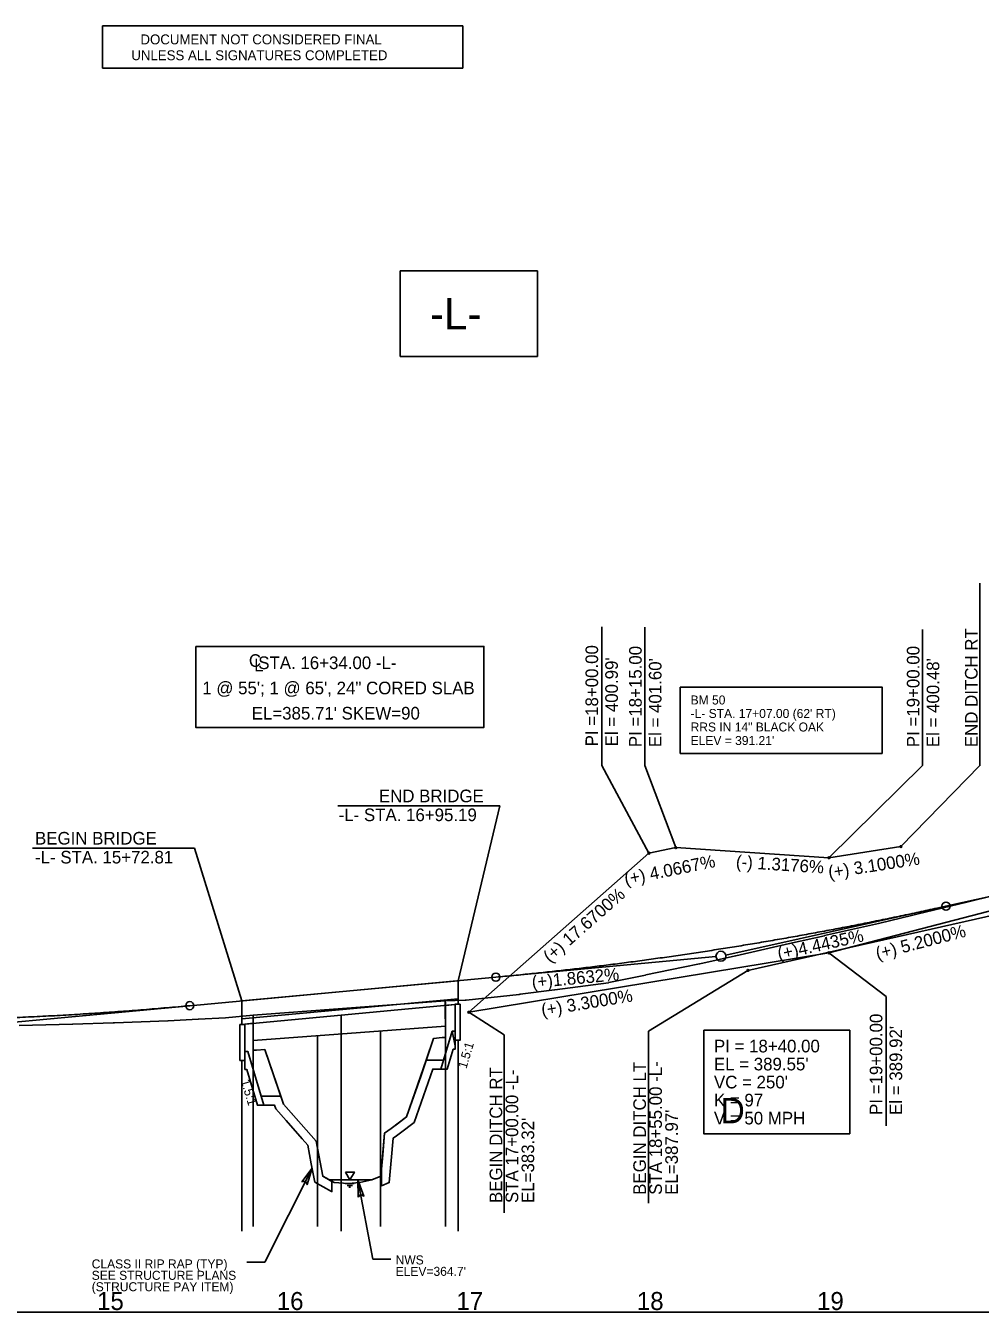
# Model space of a CAD drawing. Extents: x 2099451 to 2100919, y 990328 to 992828.
# Drawn here: x 2099966 to 2100496, y 991578 to 992293 of the extents above; entities that cross this region are included whole.
import ezdxf

# ---------------------------------------------------------------- set-up
doc = ezdxf.new("R2010")
doc.units = 0
for name, color, linetype in [('CTL Bench Mark Text', 7, 'Continuous'), ('Exist Profile Cell', 7, 'Continuous'), ('Exist Structure Major Deck Tunnel Box Culvert', 7, 'Continuous'), ('Exist Vertical Profile Ground Line', 7, 'Continuous'), ('Exist Vertical Profile Horizontal Axis Label Major', 7, 'Continuous'), ('Prop Drainage Structure Bridge', 7, 'Continuous'), ('Prop Drainage Structure Bridge Opening', 7, 'Continuous'), ('Prop Drainage Structure Bridge Opening Label', 7, 'Continuous'), ('Prop Erosion Rip Rap Class II', 7, 'Continuous'), ('Prop Plan Preparation Excavation Hatching', 7, 'Continuous'), ('Prop Plan Preparation Plan View Label', 7, 'Continuous'), ('Prop Plan Preparation Stream Water Surface', 7, 'Continuous'), ('Prop Plan Preparation Water Surface Symbol CELL', 7, 'Continuous'), ('Prop Roadway Bridge', 7, 'Continuous'), ('Prop Vertical Profile Curve Label', 7, 'Continuous'), ('Prop Vertical Profile Ditch Grade Left', 7, 'Continuous'), ('Prop Vertical Profile Ditch Grade Left Label', 7, 'Continuous'), ('Prop Vertical Profile Ditch Grade Right', 7, 'Continuous'), ('Prop Vertical Profile Ditch Grade Right Label', 7, 'Continuous'), ('Prop Vertical Profile Grade', 7, 'Continuous'), ('Prop Vertical Profile Grade Label', 7, 'Continuous'), ('Prop VPI Ditch Grade Left Label', 7, 'Continuous'), ('Prop VPI Ditch Grade Right Label', 7, 'Continuous'), ('Prop VPI Label', 7, 'Continuous'), ('Scratch_Level_2', 7, 'Continuous'), ('Typical Terminator CELL', 7, 'Continuous')]:
    doc.layers.add(name, color=color, linetype=linetype)

msp = doc.modelspace()

# ---------------------------------------------------------------- linework, layer by layer
at = {"layer": 'CTL Bench Mark Text'}
msp.add_lwpolyline([(2100329.53, 991925.5), (2100441.65, 991925.5), (2100441.65, 991888.64), (2100329.53, 991888.64)], close=True, dxfattribs=at)
at = {"layer": 'Exist Profile Cell'}
msp.add_line((2099512.14, 991578.31), (2100912.14, 991578.31), dxfattribs=at)
at = {"layer": 'Exist Structure Major Deck Tunnel Box Culvert'}
for p, q in [((2100092.35, 991743.27), (2100199.07, 991751.21)), ((2100199.12, 991750.52), (2100199.12, 991625.9)), ((2100092.4, 991742.57), (2100092.4, 991625.89)), ((2100092.38, 991729.23), (2100199.12, 991737.18)), ((2100163.11, 991734.5), (2100163.11, 991625.89)), ((2100128.15, 991731.9), (2100128.15, 991625.89))]:
    msp.add_line(p, q, dxfattribs=at)
at = {"layer": 'Exist Vertical Profile Ground Line'}
for points in [[(2100340.31, 991771.72), (2100340.37, 991771.73), (2100360.29, 991776.24), (2100360.34, 991776.26), (2100390.21, 991783.02), (2100390.32, 991783.04), (2100409.64, 991787.44), (2100409.7, 991787.45), (2100439.6, 991794.26), (2100439.66, 991794.27), (2100458.77, 991798.86), (2100461.71, 991799.57), (2100488.7, 991806.04), (2100488.78, 991806.06), (2100504.54, 991809.85)], [(2099962.4, 991737.64), (2099991.95, 991738.28), (2099992.27, 991738.29), (2100014.61, 991739.06), (2100015.06, 991739.08), (2100015.35, 991739.1), (2100044.92, 991740.11), (2100045.21, 991740.13), (2100061.86, 991740.99), (2100062.03, 991741), (2100077.04, 991741.77), (2100092.35, 991743.27), (2100092.4, 991723.81), (2100094.24, 991723.91), (2100098.82, 991724.16), (2100109.29, 991693.81), (2100127.38, 991673.31), (2100131.02, 991653.81), (2100137.32, 991650.31), (2100145.12, 991649.81), (2100151.66, 991650.31), (2100158.3, 991651.81), (2100163.2, 991653.81), (2100165.38, 991677.81), (2100169.05, 991680.31), (2100177.49, 991686.81), (2100185.66, 991709.86), (2100192.48, 991730.31), (2100197.25, 991730.81), (2100199.12, 991730.81), (2100199.07, 991751.21), (2100210.18, 991751.67), (2100210.61, 991751.71), (2100240.15, 991754.85), (2100240.18, 991754.85), (2100240.64, 991754.9), (2100259.75, 991757.41), (2100259.94, 991757.43), (2100289.62, 991761.33), (2100289.85, 991761.38), (2100310.35, 991765.58), (2100310.42, 991765.6), (2100331.26, 991769.87), (2100340.31, 991771.72)]]:
    msp.add_lwpolyline(points, dxfattribs=at)
at = {"layer": 'Prop Drainage Structure Bridge'}
for p, q in [((2100086.14, 991751.26), (2100206.14, 991762.44)), ((2100206.14, 991749.38), (2100206.14, 991762.44)), ((2100086.14, 991738.2), (2100086.14, 991751.26)), ((2100086.14, 991738.2), (2100206.14, 991749.38)), ((2100141.14, 991623.39), (2100141.14, 991743.33)), ((2100206.14, 991623.4), (2100206.14, 991729.38)), ((2100086.14, 991623.39), (2100086.14, 991718.2))]:
    msp.add_line(p, q, dxfattribs=at)
for points in [[(2100204.52, 991729.38), (2100207.27, 991729.38), (2100207.27, 991749.38), (2100204.52, 991749.38)], [(2100085.02, 991738.2), (2100087.77, 991738.2), (2100087.77, 991718.2), (2100085.02, 991718.2)]]:
    msp.add_lwpolyline(points, close=True, dxfattribs=at)
at = {"layer": 'Prop Drainage Structure Bridge Opening'}
for p, q in [((2100198.09, 991718.31), (2100188.48, 991718.31)), ((2100200.19, 991713.31), (2100196.59, 991713.31)), ((2100098.34, 991693.31), (2100094.74, 991693.31))]:
    msp.add_line(p, q, dxfattribs=at)
for points in [[(2100196.59, 991713.31), (2100202.91, 991734.38), (2100204.52, 991734.38), (2100204.52, 991724.38), (2100203.52, 991724.38), (2100200.19, 991713.31)], [(2100098.34, 991693.31), (2100089.37, 991723.2), (2100087.77, 991723.2), (2100087.77, 991713.2), (2100088.77, 991713.2), (2100094.74, 991693.31)]]:
    msp.add_lwpolyline(points, dxfattribs=at)
at = {"layer": 'Prop Erosion Rip Rap Class II'}
for points in [[(2100202.91, 991734.38), (2100204.52, 991734.38), (2100204.52, 991724.38), (2100203.52, 991724.38), (2100200.19, 991713.31), (2100196.59, 991713.31)], [(2100087.77, 991723.2), (2100089.37, 991723.2), (2100098.34, 991693.31), (2100094.74, 991693.31), (2100088.77, 991713.2), (2100087.77, 991713.2)], [(2100198.09, 991718.31), (2100188.48, 991718.31), (2100177.49, 991686.81), (2100174.17, 991684.25), (2100173.27, 991683.56), (2100169.05, 991680.31), (2100165.38, 991677.81), (2100164.29, 991665.81), (2100163.55, 991657.69), (2100163.55, 991648.55), (2100167.91, 991650.33), (2100169.03, 991662.67), (2100170.15, 991675.01), (2100171.98, 991676.26), (2100174.21, 991677.97), (2100181.71, 991683.75), (2100192.08, 991713.31), (2100196.59, 991713.31)], [(2100096.84, 991698.31), (2100107.74, 991698.31), (2100109.29, 991693.81), (2100110.75, 991692.15), (2100127.38, 991673.31), (2100129.2, 991663.56), (2100131.02, 991653.81), (2100136.14, 991650.97), (2100136.14, 991645.37), (2100135.88, 991645.39), (2100126.54, 991650.58), (2100124.63, 991660.81), (2100122.72, 991671.03), (2100119.56, 991674.61), (2100110.75, 991684.73), (2100104.89, 991691.24), (2100104.13, 991693.32), (2100098.34, 991693.31)]]:
    msp.add_lwpolyline(points, close=True, dxfattribs=at)
at = {"layer": 'Prop Plan Preparation Excavation Hatching'}
for points in [[(2100199.12, 991730.81), (2100199.12, 991748.73), (2100204.52, 991749.23), (2100204.52, 991726.32), (2100202.91, 991734.38), (2100198.09, 991718.31), (2100188.48, 991718.31), (2100192.48, 991730.31), (2100197.25, 991730.81)], [(2100087.77, 991738.36), (2100092.36, 991738.78), (2100092.4, 991723.81), (2100094.24, 991723.91), (2100098.82, 991724.16), (2100107.74, 991698.31), (2100096.84, 991698.31), (2100089.37, 991723.2), (2100087.77, 991723.2)]]:
    msp.add_lwpolyline(points, close=True, dxfattribs=at)
at = {"layer": 'Prop Plan Preparation Plan View Label'}
for p, q in [((2100125.08, 991658.37), (2100098.75, 991606.09)), ((2100150.49, 991651.81), (2100158.83, 991607.85)), ((2100098.75, 991606.09), (2100088.75, 991606.09)), ((2100158.83, 991607.85), (2100168.83, 991607.85))]:
    msp.add_line(p, q, dxfattribs=at)
msp.add_lwpolyline([(2100119.43, 991650.73), (2100125.08, 991658.37), (2100122.33, 991649.2), (2100121.38, 991651.02)], close=True, dxfattribs=at)
at = {"layer": 'Prop Plan Preparation Stream Water Surface'}
msp.add_line((2100134.62, 991651.81), (2100158.3, 991651.81), dxfattribs=at)
at = {"layer": 'Prop Plan Preparation Water Surface Symbol CELL'}
for p, q in [((2100143.49, 991649.78), (2100148.49, 991649.78)), ((2100144.49, 991648.78), (2100147.49, 991648.78)), ((2100145.49, 991647.78), (2100146.49, 991647.78))]:
    msp.add_line(p, q, dxfattribs=at)
msp.add_lwpolyline([(2100143.56, 991656.15), (2100148.56, 991656.15), (2100146.06, 991651.81)], close=True, dxfattribs=at)
at = {"layer": 'Prop Roadway Bridge'}
for p, q in [((2100206.14, 991762.44), (2100206.14, 991752.44)), ((2100206.14, 991752.44), (2100086.14, 991741.26)), ((2100086.14, 991751.26), (2100086.14, 991741.26))]:
    msp.add_line(p, q, dxfattribs=at)
at = {"layer": 'Prop Vertical Profile Curve Label'}
for centre in [(2100477.14, 991803.81), (2100227.14, 991764.4), (2100057.14, 991748.56)]:
    msp.add_circle(centre, 2.25, dxfattribs=at)
at = {"layer": 'Prop Vertical Profile Ditch Grade Left'}
msp.add_line((2100367.14, 991768.16), (2100612.14, 991823.31), dxfattribs=at)
at = {"layer": 'Prop Vertical Profile Ditch Grade Left Label'}
for p, q in [((2100367.14, 991768.16), (2100311.84, 991734.42)), ((2100311.84, 991734.42), (2100311.84, 991638.81))]:
    msp.add_line(p, q, dxfattribs=at)
at = {"layer": 'Prop Vertical Profile Ditch Grade Right'}
for points in [[(2100212.14, 991744.91), (2100312.14, 991833.26), (2100327.14, 991836.31), (2100412.14, 991830.71), (2100452.14, 991836.91)], [(2100212.14, 991744.91), (2100412.14, 991777.91), (2100612.14, 991829.91)]]:
    msp.add_lwpolyline(points, dxfattribs=at)
at = {"layer": 'Prop Vertical Profile Grade'}
for p, q in [((2100477.14, 991803.81), (2100612.14, 991833.81)), ((2100057.14, 991748.56), (2100227.14, 991764.4))]:
    msp.add_line(p, q, dxfattribs=at)
for points in [[(2100227.14, 991764.4), (2100232.14, 991764.87), (2100237.14, 991765.35), (2100242.14, 991765.85), (2100247.14, 991766.36), (2100252.14, 991766.89), (2100257.14, 991767.42), (2100262.14, 991767.97), (2100267.14, 991768.54), (2100272.14, 991769.11), (2100277.14, 991769.7), (2100282.14, 991770.3), (2100287.14, 991770.91), (2100292.14, 991771.54), (2100297.14, 991772.18), (2100302.14, 991772.83), (2100307.14, 991773.5), (2100312.14, 991774.18), (2100317.14, 991774.87), (2100322.14, 991775.58), (2100327.14, 991776.29), (2100332.14, 991777.02), (2100337.14, 991777.77), (2100342.14, 991778.52), (2100347.14, 991779.29), (2100352.14, 991780.07), (2100357.14, 991780.87), (2100362.14, 991781.68), (2100367.14, 991782.5), (2100372.14, 991783.33), (2100377.14, 991784.18), (2100382.14, 991785.04), (2100387.14, 991785.91), (2100392.14, 991786.79), (2100397.14, 991787.69), (2100402.14, 991788.6), (2100407.14, 991789.53), (2100412.14, 991790.46), (2100417.14, 991791.41), (2100422.14, 991792.37), (2100427.14, 991793.35), (2100432.14, 991794.34), (2100437.14, 991795.34), (2100442.14, 991796.35), (2100447.14, 991797.38), (2100452.14, 991798.42), (2100457.14, 991799.47), (2100462.14, 991800.54), (2100467.14, 991801.62), (2100472.14, 991802.71), (2100477.14, 991803.81)], [(2099737.14, 991745.25), (2099743.54, 991744.8), (2099749.94, 991744.37), (2099756.34, 991743.96), (2099762.74, 991743.57), (2099769.14, 991743.2), (2099775.54, 991742.85), (2099781.94, 991742.53), (2099788.34, 991742.22), (2099794.74, 991741.94), (2099801.14, 991741.67), (2099807.54, 991741.43), (2099813.94, 991741.21), (2099820.34, 991741.01), (2099826.74, 991740.84), (2099833.14, 991740.68), (2099839.54, 991740.54), (2099845.94, 991740.43), (2099852.34, 991740.34), (2099858.74, 991740.27), (2099865.14, 991740.21), (2099871.54, 991740.19), (2099877.94, 991740.18), (2099884.34, 991740.19), (2099890.74, 991740.22), (2099897.14, 991740.28), (2099903.54, 991740.36), (2099909.94, 991740.45), (2099916.34, 991740.57), (2099922.74, 991740.71), (2099929.14, 991740.88), (2099935.54, 991741.06), (2099941.94, 991741.26), (2099948.34, 991741.49), (2099954.74, 991741.73), (2099961.14, 991742), (2099967.54, 991742.29), (2099973.94, 991742.6), (2099980.34, 991742.93), (2099986.74, 991743.28), (2099993.14, 991743.66), (2099999.54, 991744.05), (2100005.94, 991744.47), (2100012.34, 991744.91), (2100018.74, 991745.36), (2100025.14, 991745.84), (2100031.54, 991746.34), (2100037.94, 991746.87), (2100044.34, 991747.41), (2100050.74, 991747.97), (2100057.14, 991748.56)]]:
    msp.add_spline(points, degree=3, dxfattribs=at)
at = {"layer": 'Prop VPI Ditch Grade Left Label'}
msp.add_circle((2100367.14, 991768.16), 0.5, dxfattribs=at)
at = {"layer": 'Prop VPI Ditch Grade Right Label'}
for p, q in [((2100495.93, 991983.15), (2100495.93, 991881.72)), ((2100285.93, 991959.03), (2100285.93, 991881.93)), ((2100309.87, 991958.83), (2100309.87, 991881.93)), ((2100464.15, 991957.41), (2100464.15, 991881.93)), ((2100312.14, 991833.26), (2100285.93, 991881.93)), ((2100327.14, 991836.31), (2100309.87, 991881.93)), ((2100412.14, 991830.71), (2100464.15, 991881.93)), ((2100452.14, 991836.91), (2100495.93, 991881.93)), ((2100412.14, 991777.91), (2100443.99, 991753.7)), ((2100443.99, 991753.7), (2100443.99, 991681.78)), ((2100212.14, 991744.91), (2100231.71, 991732.45)), ((2100231.71, 991732.45), (2100231.71, 991633.46))]:
    msp.add_line(p, q, dxfattribs=at)
for centre in [(2100312.14, 991833.26), (2100327.14, 991836.31), (2100452.14, 991836.91), (2100412.14, 991830.71), (2100412.14, 991777.91), (2100212.14, 991744.91), (2100212.14, 991744.91)]:
    msp.add_circle(centre, 0.5, dxfattribs=at)
at = {"layer": 'Prop VPI Label'}
for p, q in [((2100229.39, 991859.58), (2100139.39, 991859.58)), ((2100206.14, 991762.44), (2100229.39, 991859.58)), ((2100059.86, 991836.08), (2099969.86, 991836.08)), ((2100086.14, 991751.26), (2100059.86, 991836.08)), ((2100477.14, 991803.81), (2100354.83, 991776.64)), ((2100227.14, 991764.4), (2100349.4, 991775.79)), ((2100057.14, 991748.56), (2099899.88, 991733.91))]:
    msp.add_line(p, q, dxfattribs=at)
for points in [[(2100174.09, 992156.57), (2100250.2, 992156.57), (2100250.2, 992109.11), (2100174.09, 992109.11)], [(2100060.5, 991948.1), (2100220.5, 991948.1), (2100220.5, 991903.1), (2100060.5, 991903.1)], [(2100342.63, 991734.92), (2100423.74, 991734.92), (2100423.74, 991677.46), (2100342.63, 991677.46)]]:
    msp.add_lwpolyline(points, close=True, dxfattribs=at)
msp.add_circle((2100352.14, 991776.04), 2.75, dxfattribs=at)
at = {"layer": 'Scratch_Level_2'}
for p, q in [((2100008.69, 992269.24), (2100008.69, 992292.74)), ((2100008.69, 992292.74), (2100208.72, 992292.74)), ((2100208.72, 992292.73), (2100208.72, 992269.23)), ((2100208.72, 992269.24), (2100008.69, 992269.24))]:
    msp.add_line(p, q, dxfattribs=at)
at = {"layer": 'Typical Terminator CELL'}
msp.add_lwpolyline([(2100150.65, 991642.3), (2100150.49, 991651.81), (2100153.89, 991642.86), (2100152.03, 991643.72)], close=True, dxfattribs=at)

# ---------------------------------------------------------------- texts
at = {"layer": 'CTL Bench Mark Text'}
for s, p in [('BM 50', (2100335.32, 991915.82)), ("-L- STA. 17+07.00 (62' RT)", (2100335.32, 991908.32)), ('RRS IN 14" BLACK OAK', (2100335.32, 991900.82)), ("ELEV = 391.21'", (2100335.32, 991893.32))]:
    msp.add_text(s, height=5, rotation=360, dxfattribs=at).set_placement(p)
at = {"layer": 'Exist Vertical Profile Horizontal Axis Label Major'}
for s, p in [('15', (2100005.63, 991579.56)), ('16', (2100105.46, 991579.56)), ('17', (2100205.2, 991579.56)), ('18', (2100305.44, 991579.56)), ('19', (2100405.51, 991579.56))]:
    msp.add_text(s, height=10, dxfattribs=at).set_placement(p)
at = {"layer": 'Prop Drainage Structure Bridge Opening Label'}
for rotation, p in [(73.30076, (2100210.77, 991713.25)), (286.69924, (2100085.46, 991706.88))]:
    msp.add_text('1.5:1', height=5, rotation=rotation, dxfattribs=at).set_placement(p)
at = {"layer": 'Prop Plan Preparation Plan View Label'}
for s, p in [('CLASS II RIP RAP (TYP)', (2100002.68, 991602.66)), ('NWS', (2100171.5, 991604.87)), ('SEE STRUCTURE PLANS', (2100002.68, 991596.33)), ("ELEV=364.7'", (2100171.5, 991598.53)), ('(STRUCTURE PAY ITEM)', (2100002.68, 991589.99))]:
    msp.add_text(s, height=5, dxfattribs=at).set_placement(p)
at = {"layer": 'Prop Vertical Profile Curve Label'}
for s, height, p in [('-L-', 17.5, (2100190.55, 992124.09)), ("VC = 250'", 7, (2100348.28, 991702.63)), ('K = 97', 7, (2100348.28, 991692.63)), ('D', 14, (2100351.89, 991683.26)), ('V = 50 MPH', 7, (2100348.28, 991682.63))]:
    msp.add_text(s, height=height, dxfattribs=at).set_placement(p)
at = {"layer": 'Prop Vertical Profile Ditch Grade Right Label'}
for s, rotation, p in [('(+) 4.0667%', 11.49345, (2100299.27, 991815.42)), ('(-) 1.3176%', 356.23067, (2100360.33, 991825.18)), ('(+) 3.1000%', 8.81073, (2100412.32, 991819.13)), ('(+) 17.6700%', 41.4606, (2100257.26, 991772.02)), ('(+) 5.2000%', 14.57422, (2100439.14, 991774.08)), ('(+) 3.3000%', 9.36939, (2100252.96, 991742.62))]:
    msp.add_text(s, height=7, rotation=rotation, dxfattribs=at).set_placement(p)
at = {"layer": 'Prop Vertical Profile Grade Label'}
for s, rotation, p in [('(+)4.4435%', 12.52633, (2100384.41, 991773.81)), ('(+)1.8632%', 5.32228, (2100247.43, 991758.2))]:
    msp.add_text(s, height=7, rotation=rotation, dxfattribs=at).set_placement(p)
at = {"layer": 'Prop VPI Ditch Grade Left Label'}
for s, p in [('BEGIN DITCH LT', (2100310.5, 991643.53)), ('STA 18+55.00 -L-', (2100319.37, 991643.53)), ("EL=387.97'", (2100328.25, 991643.53))]:
    msp.add_text(s, height=7, rotation=90, dxfattribs=at).set_placement(p)
at = {"layer": 'Prop VPI Ditch Grade Right Label'}
for s, p in [('END DITCH RT', (2100494.7, 991892.12)), ('PI =18+00.00', (2100283.93, 991892.57)), ('PI =18+15.00', (2100308.14, 991892.12)), ('PI =19+00.00', (2100462.42, 991892.12)), ("El = 400.99'", (2100294.93, 991892.57)), ("El = 401.60'", (2100319.14, 991892.12)), ("El = 400.48'", (2100473.42, 991892.12)), ('PI =19+00.00', (2100441.81, 991687.91)), ("El = 389.92'", (2100452.81, 991687.91)), ('BEGIN DITCH RT', (2100230.68, 991638.99)), ('STA 17+00.00 -L-', (2100239.56, 991638.99)), ("EL=383.32'", (2100248.43, 991638.99))]:
    msp.add_text(s, height=7, rotation=90, dxfattribs=at).set_placement(p)
at = {"layer": 'Prop VPI Label'}
for s, p in [('C', (2100089.98, 991936.71)), ('  STA. 16+34.00 -L-', (2100090, 991935.48)), ('1 @ 55\'; 1 @ 65\', 24" CORED SLAB', (2100064.09, 991921.48)), ("EL=385.71' SKEW=90", (2100091.56, 991907.48)), ('END BRIDGE', (2100162.19, 991861.54)), ('-L- STA. 16+95.19', (2100139.83, 991851.04)), ('BEGIN BRIDGE', (2099971.22, 991838.04)), ('-L- STA. 15+72.81', (2099971.22, 991827.54)), ('PI = 18+40.00', (2100348.28, 991722.63)), ("EL = 389.55'", (2100348.28, 991712.63))]:
    msp.add_text(s, height=7, dxfattribs=at).set_placement(p)
msp.add_text('L', height=7, rotation=359.9469, dxfattribs=at).set_placement((2100092.89, 991934.26))
at = {"layer": 'Scratch_Level_2'}
for s, p in [('DOCUMENT NOT CONSIDERED FINAL', (2100029.76, 992282.4)), ('UNLESS ALL SIGNATURES COMPLETED', (2100024.69, 992273.6))]:
    msp.add_text(s, height=5.5, dxfattribs=at).set_placement(p)

doc.saveas('drawing.dxf')
